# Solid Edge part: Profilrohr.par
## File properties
Username: bmolnar
Dokumentum tartalom típus: 0
Author: bmolnar
Last saved by: bmolnar
Revision: 78
Sűrűség: 0,000 kg/m^3
Pontosság: 0,990
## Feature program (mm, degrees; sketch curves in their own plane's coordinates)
base feature "unnamed BaseFeature 1"
thread "unnamed Thread 1"
thread "Menet_2"  ThreadDepth = 9.3 mm
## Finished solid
Body 1: solid body, 177 faces, 414 edges, 259 vertices, 3 separate solids.
  Faces by surface: plane 86, cylinder 71, cone 16, torus 4
  Edges by curve: line 240, circle 166, curve on surface 8
Bounding box of the edges (mm; curved faces can reach further): 100.000 x 105.000 x 61.000, from (-50, -50, 0) to (50, 55, 61).
Cylindrical faces by radius (mm): R0.2 x24, R2.15 x2, R4 x2, R4.5 x4, R5.5 x4, R5.7225 x4, R6.9 x2, R7 x8, R8.5 x8, R40 x1, R40.1 x2, R40.85 x2, R41.05 x2, R42.8 x2, R67.3474 x1, R67.5 x3
Conical faces (half-angle, radius in mm at the cone's reference point): 30 deg R40.325 x2, 30 deg R41.1387 x2, 45 deg R4.25 x4, 45 deg R6.0725 x2, 45 deg R6.65 x4, 45 deg R41.15 x2
Toroidal faces (ring radius, tube radius in mm): R42.6 r0.2 x4
Planar faces by outward normal: +x 9, +y 11, +z 13, -x 9, -y 9, -z 11, oblique 24
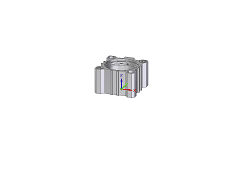
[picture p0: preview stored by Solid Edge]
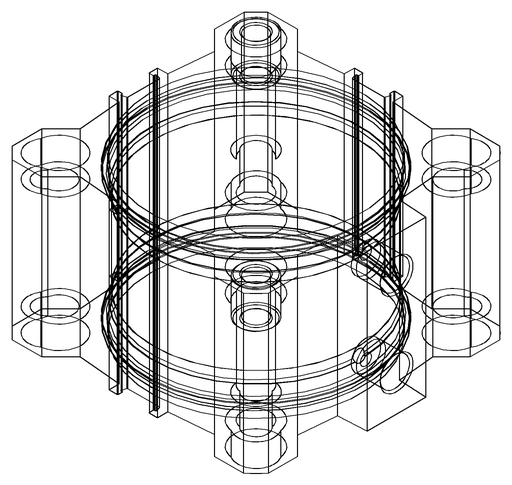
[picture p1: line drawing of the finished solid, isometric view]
